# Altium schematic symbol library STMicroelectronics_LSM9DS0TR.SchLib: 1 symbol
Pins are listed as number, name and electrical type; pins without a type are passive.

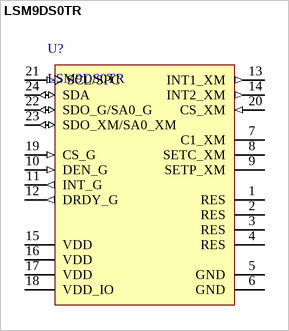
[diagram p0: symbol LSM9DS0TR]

## LSM9DS0TR
designator U?
INEMO Inertial Module: 3D Accelerometer, 3D Gyroscope, 3D Magnetometer, 2.4 to 3.6 V, -40 to 85 degC, 24-Pin LGA, RoHS, Tape and Reel; Manufacturer: STMicroelectronics; IDD_PDN: 6 uA Typ.; IDD_G_LP: 2 mA Typ.; VDDIO: 1.71 V Min.; IDD_XM: 350 uA Typ.; Bandwidth: 400 kHz; IDD_G: 6.1 mA Typ.
footprint STM-LGA-24_V
pins: 1 RES "Leave unconnected", 2 RES "Connect to GND", 3 RES "Connect to GND", 4 RES "Connect to GND", 5 GND (power) "0 V supply", 6 GND (power) "0 V supply", 7 C1_XM "Capacitor connection (C1)", 8 SETC_XM "S/R capacitor connection (C2)", 9 SETP_XM "S/R capacitor connection (C2)", 10 DEN_G (in) "Gyroscope data enable", 11 INT_G (out) "Gyroscope programmable interrupt", 12 DRDY_G (out) "Gyroscope data ready", 13 INT1_XM (out) "Accelerometer and magnetic sensor interrupt 1", 14 INT2_XM (out) "Accelerometer and magnetic sensor interrupt 2", 15 VDD (power) "Power supply", 16 VDD (power) "Power supply", 17 VDD (power) "Power supply", 18 VDD_IO (power) "Power supply for I/O pins", 19 CS_G (in) "Gyroscope I2C/SPI mode selection, 1: SPI idle mode / I2C communication enabled, 0: SPI communication mode / I2C disabled", 20 CS_XM (in) "Accelerometer and magnetic sensor SPI enabled, I2C/SPI mode selection, 1: SPI idle mode / I2C communication enabled, 0: SPI communication mode / I2C disabled", 21 SCL/SPC (in), 22 SDO_G/SA0_G (io), 23 SDO_XM/SA0_XM (io), 24 SDA (io) "I2C serial data (SDA)"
